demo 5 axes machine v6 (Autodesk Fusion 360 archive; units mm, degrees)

design "demo 5 axes machine" references "haas umc-500ss", "IUT GMP BESANCON 5AX130"
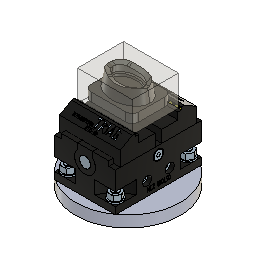
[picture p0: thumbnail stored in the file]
parameter "Ouverture" = 53
sketch "Esquisse1" plane through (0, 0, 0) normal (0, 0, 1) x axis (1, 0, 0)
  line L1 (-27.5, 22.5) -> (27.5, 22.5)
  line L2 (-27.5, -22.5) -> (-27.5, 22.5)
  line L3 (27.5, -22.5) -> (-27.5, -22.5)
  line L4 (27.5, 22.5) -> (27.5, -22.5)
  line L5 (-27.5, -22.5) -> (27.5, 22.5)
  line L6 (27.5, -22.5) -> (-27.5, 22.5)
  point P6 (0, 0)
  point P1 (0, 0)
  point P4 (-27.5, -22.5)
  point P5 (27.5, -22.5)
  point P3 (-27.5, 22.5)
  horizontal L1
  perpendicular L1 L2
  parallel L1 L3
  parallel L2 L4
  coincident L5 P6
  coincident L6 P6
  coincident P1 P6
  dimension "d1" distance P4 P5 = 55
  dimension "d2" distance P3 P4 = 45
extrude "Extrusion1" new body sketch "Esquisse1" profile of L1 L2 L3 L4 along normal blind 10
work_plane "Plan de construction1" AlongDistance 0
sketch "Esquisse2" plane through (0, 0, 10) normal (0, 0, 1) x axis (1, 0, 0)
  curve K1 (-25.2272, 0) -> (25.2272, 0)
  curve K2 (0, -18.3421) -> (0, 18.3421)
  line L1 (27.5, 22.5) -> (27.5, -22.5)
  closed curve K3 centre (0, 0)
  point P3 (25.2272, 0)
  point P4 (-25.2272, 0)
  point P5 (0, 18.3421)
  point P6 (0, -18.3421)
  point P1 (0, 0)
  point P2 (0, 0)
  coincident K3 P3
  coincident K3 P4
  coincident K3 P5
  coincident K3 P6
  coincident P1 P2
  perpendicular K1 L1
extrude "Extrusion2" add sketch "Esquisse2" profile of K3 along normal blind 20
work_plane "Plan de construction2" AlongDistance 0
sketch "Esquisse3" plane through (-0.1761, -0.02, 30) normal (0, 0, 1) x axis (1, 0, 0)
  dimension "d9" distance = 5
extrude "Extrusion3" cut sketch "Esquisse3" against normal blind 12
extrude "Extrusion4" cut sketch "Esquisse3" against normal blind 15
sketch "Esquisse4" plane through (0, 0, 0) normal (0, 1, 0) x axis (1, 0, 0)
  line L1 (-18.831, -18) -> (-16.7151, -30)
  line L2 (16.7006, -30) -> (18.8166, -18)
  line L3 (13.5725, -17.0753) -> (18.8166, -18)
  line L4 (13.5725, -17.0753) -> (16.7006, -30)
  point P4 (18.8166, -18)
  point P6 (18.8166, -18)
  point P5 (16.7006, -30)
  point P8 (16.7006, -30)
  coincident P4 P6
  perpendicular L2 L3
  coincident P5 P8
sweep "Balayage1" sketch "Esquisse4"
sketch "Esquisse5" plane through (0, 0, 0) normal (0, 1, 0) x axis (1, 0, 0)
  line L1 (-25.8214, -28.6389) -> (-53.5169, -31.6416)
  line L2 (-7.691, -23.6425) -> (-9.5908, -24.4416)
  line L3 (29.3071, -29.376) -> (16.0246, -23.7058)
  arc A1 centre (-32.0714, 29.0081) radius 57.9849 clockwise from (-9.5908, -24.4416) to (-25.8214, -28.6389)
  arc A2 centre (4.0921, -51.6579) radius 30.3925 clockwise from (-7.691, -23.6425) to (16.0246, -23.7058)
  tangent L1 A1
  tangent A1 L2
  tangent L2 A2
  tangent A2 L3
work_plane "Plan de construction3"
sketch "Esquisse6" plane through (29.3071, 0, 29.376) normal (0.9197, 0, 0.3926) x axis (0, 1, 0)
  line L1 (-3.3255, -1.3207) -> (-104.8059, 44.2386)
  line L2 (94.45, 37.8653) -> (3.1087, -1.3729)
  line L3 (0, 43.8926) -> (0, 0)
  arc A1 centre (-0.0489, 5.9775) radius 8 clockwise from (3.1087, -1.3729) to (-3.3255, -1.3207)
  point P1 (0, 0)
  point P7 (0, 0)
  tangent L1 A1
  tangent A1 L2
  coincident P1 P7
  vertical L3
  dimension "d35" radius A1 = 8
sweep "Balayage2"
split "Scinder" bodies "PIECE  axes"
fillet "Congé" radius 7.5
sketch "Esquisse7" plane through (0, 0, 0) normal (0, 0, 1) x axis (1, 0, 0)
  line L1 (31.5, -26.5) -> (-31.5, -26.5)
  line L2 (31.5, 26.5) -> (31.5, -26.5)
  line L3 (-31.5, 26.5) -> (31.5, 26.5)
  line L4 (-31.5, -26.5) -> (-31.5, 26.5)
  line L5 (31.5, 26.5) -> (-31.5, -26.5)
  line L6 (-31.5, 26.5) -> (31.5, -26.5)
  point P6 (0, 0)
  point P1 (0, 0)
  point P4 (31.5, 26.5)
  point P5 (-31.5, 26.5)
  point P3 (31.5, -26.5)
  horizontal L1
  perpendicular L1 L2
  parallel L1 L3
  parallel L2 L4
  coincident L5 P6
  coincident L6 P6
  coincident P1 P6
  dimension "d29" distance P4 P5 = 63
  dimension "d30" distance P3 P4 = 53
extrude "Extrusion5" new body sketch "Esquisse7" profile of L1 L2 L3 L4 along normal blind 30 and against normal blind 5 "d34" 0 (= "Side2TaperAngle") bodies "BRUT"
base_feature "Base Feature1" sketch "Esquisse3"
base_feature "Base Feature1" sketch "Esquisse3"
base_feature "Base Feature1" sketch "Esquisse3"
position "Position1"
joint_origin "JointOrigin1" OffsetX 0 named "d1_1" OffsetY 0 named "d2_1" OffsetZ 0 named "d3_1"
joint_origin "JointOrigin2" OffsetX 0 named "d5_1" OffsetY 0 named "d6_1" OffsetZ 0 named "d7_1"
joint_origin "JointOrigin1" OffsetX 0 named "d9_1" OffsetY 0 named "d10_1" OffsetZ 0 named "d11_1"
joint "Assemble1" alignOffsetX 0 named "d14_1" alignOffsetY 0 named "d15_1" alignOffsetZ -3.8 (= "-Ouverture / 2 + 22.7 mm") named "d16_1"
joint "Assemble2" alignOffsetX 0 named "d23_1" alignOffsetY 0 named "d24_1" alignOffsetZ 3.8 (= "Ouverture / 2 - 22.7 mm") named "d25_1"
position "Position3"
component_from_bodies "Corps->Comp1"
component_from_bodies "Corps->Comp2"
position "Position4"
as_built_joint "Réelle"
position "Position5"
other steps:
base_feature "Fonction de base1" bodies "PIECE  axes"
base_feature "Fonction de base1" bodies "BRUT"
create_component "CreateComponent1"
create_component "CreateComponent2"
create_component "CreateComponent3"
joint_origin "JointOrigin2" OffsetX 0 named "d18_1" OffsetY 0 named "d19_1" OffsetZ 0 named "d20_1"
create_component "CreateComponent2"
create_component "CreateComponent3"
remove_body "RemoveBody2"
create_component "CreateComponent4"
remove_body "RemoveBody3"
named bodies: "BRUT", "PIECE  axes"

design "haas umc-500ss"
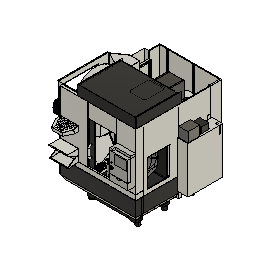
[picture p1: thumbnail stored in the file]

design "IUT GMP BESANCON 5AX130"
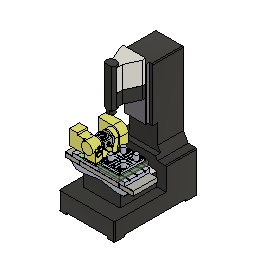
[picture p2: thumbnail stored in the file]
